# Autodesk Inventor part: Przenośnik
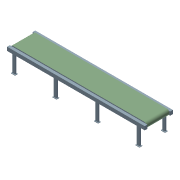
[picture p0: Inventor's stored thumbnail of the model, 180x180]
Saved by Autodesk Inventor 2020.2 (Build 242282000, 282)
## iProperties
Created: 2006-01
Part Number: Przenośnik
Document SubType Name: Modeling
Designer: F.Stasiak
Stock Number: Przenośnik
Density: 1 g/cm^3
Material: Ogólny
Appearance: Niebieski pastelowy
Manager: www.cadconsulting.pl
Company: Fabian Stasiak CAD Consulting
Author: F.Stasiak
Subject: Zbiór ćwiczeń. Autodesk Inventor 2020. Kurs podstawowy
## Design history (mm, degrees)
sketch "Szkic1"
  geometry: L1 (6000, -500)-(6000, 500); L2 (6000, 500)-(0, 500); L3 (6000, -500)-(0, -500); L4 (0, -500)-(0, 500); 2 further points
  constraints: 8 end point, 3 perpendicular, 1 coincident, 1 midpoint, 1 vertical
  dimensions: "d0" = 6000 distance of L1.end L2.end; "d22" = 1000 distance of L3.end L2.end
extrude "Wyciągnięcie proste1" new body sketch "Szkic1" distance "d2" = 240; taper "d3" = 0 deg
fillet "Zaokrąglenie1" dims "d4" = 120
sketch "Szkic5"
  geometry: L1 (-150, 200)-(5910, 200); L2 (5910, 200)-(5910, 40); L3 (5910, 40)-(-150, 40); L4 (-150, 40)-(-150, 200); L5 (-150, 120)-(5910, 120); A1 r 120 centre (0, 120) between (0, 240) and (0, 0) reference; A2 r 120 centre (5760, 120) between (5760, 0) and (5760, 240) reference
  constraints: 10 end point, 2 midpoint, 2 parallel, 2 point on line, 1 horizontal, 1 perpendicular
  dimensions: "d23" = 160 distance of L1.end L2.end; "d24" = 150 distance from line of A2.centre L2; "d25" = 150 distance from line of A1.centre L4
extrude "Wyciągnięcie proste5" join sketch "Szkic5" distance "d26" = 120; taper "d27" = 0 deg
sketch "Szkic6"
  geometry: L1 (5860, 30)-(5740, 30); L2 (5740, 30)-(5740, 90); L3 (5740, 90)-(5860, 90); L4 (5860, 90)-(5860, 30); L5 (0, 0)-(6060, 0) reference; L6 (6060, 120)-(6060, 0) reference
  constraints: 8 end point, 2 parallel, 1 horizontal, 1 perpendicular
  dimensions: "d28" = 120 distance of L1.start L1.end; "d29" = 60 distance of L3.end L1.start; "d30" = 30 distance between parallel lines of L5 L1; "d31" = 200 distance between parallel lines of L6 L4
extrude "Wyciągnięcie proste6" join sketch "Szkic6" distance "d32" = 750; taper "d33" = 0 deg
sketch "Szkic7"
  geometry: L1 (5740, 30)-(5740, 90) reference; L2 (5860, 30)-(5740, 30) reference; L3 (5860, 90)-(5860, 30) reference; L4 (5740, 90)-(5860, 90) reference; L5 (5890, 120)-(5890, 0); L6 (5890, 0)-(5710, 0); L7 (5710, 0)-(5710, 120); L8 (5710, 120)-(5890, 120)
  constraints: 8 end point, 3 other
  dimensions: "d34" = 30 distance between parallel lines of L4 L8
extrude "Wyciągnięcie proste7" join sketch "Szkic7" distance "d35" = 20; taper "d36" = 0 deg
pattern_linear "Szyk prostokątny2" dims "d39" = 5480 (computed from d0)
mirror "Lustro1"
node "Bryła1"
node "Korpusy bryłowe"
node "Korpusy powierzchniowe"
node "Pętla rzutowana1"
